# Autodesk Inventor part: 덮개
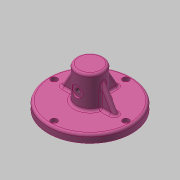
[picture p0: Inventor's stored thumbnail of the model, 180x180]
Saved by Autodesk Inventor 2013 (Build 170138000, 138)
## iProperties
Created: 2017-08
Part Number: 덮개
Material: 알루미늄 6061
Document SubType Name: Modeling
Designer: mduedu
Density: 2.71 g/cm^3
Mass: 331.485 g
Surface Area: 305.526 cm^2
Volume: 122.319 cm^3
Author: mduedu
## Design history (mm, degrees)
sketch "스케치1"
  geometry: C1 r 52.5 at (0, 0); 1 further point
  constraints: 1 centre point, 1 coincident
  dimensions: "d55" = 105 diameter of C1
extrude "돌출1" new body sketch "스케치1" distance "d5" = 10; taper "d6" = 0 deg
sketch "스케치2"
  geometry: C1 r 17 at (0, 0); 1 further point
  constraints: 1 centre point, 1 coincident
  dimensions: "d74" = 34 diameter of C1
extrude "돌출2" join sketch "스케치2" distance "d9" = 40; taper "d10" = 0 deg
sketch "스케치3"
  geometry: C1 r 37 at (0, 0); 1 further point
  constraints: 1 centre point, 1 coincident
  dimensions: "d56" = 74 diameter of C1
extrude "돌출3" join sketch "스케치3" distance "d12" = 8; taper "d13" = 0 deg
sketch "스케치4"
  geometry: C1 r 33 at (0, 0); 1 further point
  constraints: 1 centre point, 1 coincident
  dimensions: "d57" = 66 diameter of C1
extrude "돌출4" cut sketch "스케치4" distance "d16" = 7; taper "d17" = 0 deg
sketch "스케치5"
  geometry: C1 r 9 at (0, 0); 1 further point
  constraints: 1 centre point, 1 coincident
  dimensions: "d18" = 18 diameter of C1
extrude "돌출5" cut sketch "스케치5" distance "d19" = 47; taper "d20" = 0 deg
node "작업 평면1"
sketch "스케치11"
  geometry: L1 (-52.5, -10)-(52.5, -10) reference; 2 further points
  constraints: 1 vertical alignment
  dimensions: "d78" = 28 distance from line of point (0, 18) L1
hole "구멍5" sketch "스케치11" at (0, 18) diameter "d79" = 5.917; stored, may be unused: countersink angle "d83" = 90 deg, drill point angle "d85" = 118 deg; dims "d80" = 6, "d81" = 14, "d82" = 2, "d84" = 8
fillet "모깎기9" dims "d86" = 3
fillet "모깎기5" dims "d40" = 1
sketch "스케치12"
  geometry: C1 r 2.5 at (0, 0); 1 further point
  constraints: 1 centre point, 1 coincident
  dimensions: "d87" = 5 diameter of C1
extrude "돌출6" join sketch "스케치12" distance "d88" = 3; taper "d89" = 0 deg
fillet "모깎기10" dims "d91" = 1
chamfer "모따기1" distance "d41" = 1; stored, may be unused: second distance "d42" = 2, angle "d43" = 45 deg
fillet "모깎기7" dims "d45" = 3
fillet "모깎기8" dims "d46" = 3
sketch "스케치10" dims "d59" = 90
  geometry: 3 further points
  constraints: 2 vertical alignment, 1 coincident, 2 other
hole "구멍4" sketch "스케치10" at (0, 45) diameter "d60" = 4.5; stored, may be unused: countersink angle "d64" = 90 deg, drill point angle "d66" = 118 deg; dims "d61" = 6, "d62" = 8, "d63" = 4.6, "d65" = 8
sketch "스케치13"
  geometry: L1 (52.5, 7)-(52.5, 0) reference; L2 (52.5, 0)-(47.25, 0) reference; L3 (47.25, 0)-(47.25, 5.4) reference; L4 (47.25, 5.4)-(49, 5.4) reference; L5 (49, 5.4)-(49, 10) reference; L6 (49, 10)-(49.5, 10) reference; L7 (-49.5, 10)-(-49, 10) reference; L8 (-49, 10)-(-49, 5.4) reference; L9 (-49, 5.4)-(-47.25, 5.4) reference; L10 (-47.25, 5.4)-(-47.25, 0) reference; L11 (-47.25, 0)-(-52.5, 0) reference; L12 (-52.5, 0)-(-52.5, 7) reference; L13 (-3.5, 46)-(-8, 46) reference; L14 (-9, 45)-(-9, -1) reference; L15 (-9, -1)-(-30, -1) reference; L16 (-33, -4)-(-33, -8) reference; L17 (-33, -8)-(-36, -8) reference; L18 (-36, -8)-(-37, -7) reference; L19 (-37, -7)-(-37, 0) reference; L20 (-37, 0)-(-42.75, 0) reference; L21 (-42.75, 0)-(-42.75, 5.4) reference; L22 (-42.75, 5.4)-(-41, 5.4) reference; L23 (-41, 5.4)-(-41, 10) reference; L24 (-41, 10)-(-20, 10) reference; L25 (-17, 13)-(-17, 47) reference; L26 (-14, 50)-(14, 50) reference; L27 (17, 47)-(17, 13) reference; L28 (20, 10)-(41, 10) reference; L29 (41, 10)-(41, 5.4) reference; L30 (41, 5.4)-(42.75, 5.4) reference; L31 (42.75, 5.4)-(42.75, 0) reference; L32 (42.75, 0)-(37, 0) reference; L33 (37, 0)-(37, -7) reference; L34 (37, -7)-(36, -8) reference; L35 (36, -8)-(33, -8) reference; L36 (33, -8)-(33, -4) reference; L37 (30, -1)-(9, -1) reference; L38 (9, -1)-(9, 45) reference; L39 (8, 46)-(3.5, 46) reference; L40 (2.5, 45)-(2.5, 43) reference; L41 (2.5, 43)-(-2.5, 43) reference; L42 (-2.5, 43)-(-2.5, 45) reference; L43 (17, 40)-(34.321, 10); L44 (-49.5, 10)-(49.5, 10) reference; A1 r 3 centre (49.5, 7) between (52.5, 7) and (49.5, 10) reference; A2 r 3 centre (-49.5, 7) between (-49.5, 10) and (-52.5, 7) reference; A3 r 1 centre (-3.5, 45) between (-2.5, 45) and (-3.5, 46) reference; A4 r 1 centre (-8, 45) between (-8, 46) and (-9, 45) reference; A5 r 3 centre (-30, -4) between (-30, -1) and (-33, -4) reference; A6 r 3 centre (-20, 13) between (-20, 10) and (-17, 13) reference; A7 r 3 centre (-14, 47) between (-14, 50) and (-17, 47) reference; A8 r 3 centre (14, 47) between (17, 47) and (14, 50) reference; A9 r 3 centre (20, 13) between (17, 13) and (20, 10) reference; A10 r 3 centre (30, -4) between (33, -4) and (30, -1) reference; A11 r 1 centre (8, 45) between (9, 45) and (8, 46) reference; A12 r 1 centre (3.5, 45) between (3.5, 46) and (2.5, 45) reference; 1 further point
  constraints: 2 end point, 2 point on line
  dimensions: "d98" = 120 deg angle of L43 L28; "d99" = 30 distance from line of L43.start L44
feature "리브1" sketch "스케치13" dims "d100" = 1, "d101" = 6, "d102" = 0, "d103" = 0, "d104" = 1, "d105" = 1
fillet "모깎기11" dims "d106" = 3
fillet "모깎기12" dims "d107" = 3
node "솔리드1"
pattern_circular "원형 패턴1" dims angle "d68" = 360 deg
pattern_circular "원형 패턴2" dims "d109" = 270 deg
node "절단 모서리 투영1"
